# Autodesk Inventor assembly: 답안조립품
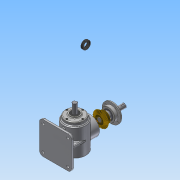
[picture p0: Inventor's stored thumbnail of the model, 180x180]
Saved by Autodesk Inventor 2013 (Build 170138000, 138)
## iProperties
Created: 2015-07
Part Number: 답안조립품
Document SubType Name: Assembly
Designer: Administrator
Author: Administrator
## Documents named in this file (14)
- C:\Users\Administrator\Desktop\450706V1023\답안조립품.iam
- C:\Users\Administrator\Desktop\450706V1023\본체.ipt
- C:\Users\Administrator\Desktop\450706V1023\M4.ipt
- C:\Users\Administrator\Desktop\450706V1023\메인 베벨기어.ipt
- C:\Users\Administrator\Desktop\450706V1023\메인 축.ipt
- 메인 축.ipt
- C:\Users\Administrator\Desktop\450706V1023\베어링 6203.ipt
- C:\Users\Administrator\Desktop\450706V1023\서브 베벨기어.ipt
- C:\Users\Administrator\Desktop\450706V1023\서브 축.ipt
- 서브 축.ipt
- C:\Users\Administrator\Desktop\450706V1023\오일실.ipt
- C:\Users\Administrator\Desktop\450706V1023\커버.ipt
- C:\Users\Administrator\Desktop\450706V1023\키 4x4.ipt
- C:\Users\Administrator\Desktop\450706V1023\키 5x5.ipt
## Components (4 placed, 1 different names)
1. M4:1
2. M4:2
3. M4:3
4. M4:4
